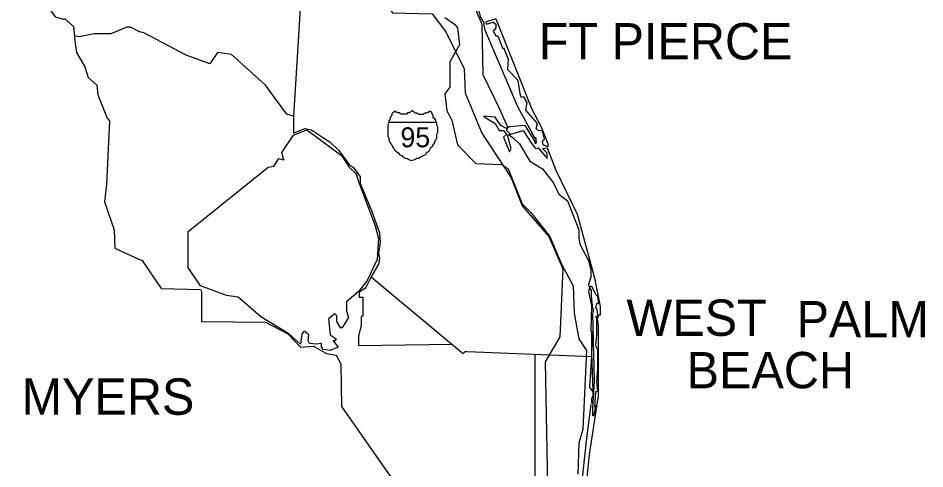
# Model space of a CAD drawing. Extents: x -820.2 to -798.1, y -2199.1 to -2182.2.
# Drawn here: x -805.79 to -804.667, y -2185.475 to -2184.917 of the extents above; entities that cross this region are included whole.
import ezdxf

# ---------------------------------------------------------------- set-up
doc = ezdxf.new("R2010")
doc.units = 0
for name, color, linetype in [('FLMap1', 7, 'Continuous'), ('FLMap2', 7, 'Continuous'), ('FLMap3', 7, 'Continuous'), ('TextMisc', 7, 'Continuous')]:
    doc.layers.add(name, color=color, linetype=linetype)

msp = doc.modelspace()

# ---------------------------------------------------------------- linework, layer by layer
at = {"layer": 'FLMap1'}
msp.add_line((-805.3303, -2185.0458), (-805.2728, -2185.0458), dxfattribs=at)
for points in [[(-805.3016, -2185.0319), (-805.3025, -2185.0319), (-805.304, -2185.0334), (-805.305, -2185.0344), (-805.3065, -2185.0344), (-805.3075, -2185.0344), (-805.3085, -2185.0358), (-805.31, -2185.0358), (-805.312, -2185.0358), (-805.3135, -2185.0358), (-805.3145, -2185.0358), (-805.3159, -2185.0358), (-805.3169, -2185.0344), (-805.3194, -2185.0344), (-805.3204, -2185.0334), (-805.3219, -2185.0334), (-805.3234, -2185.0319), (-805.3244, -2185.0334), (-805.3259, -2185.0344), (-805.3269, -2185.0358), (-805.3269, -2185.0368), (-805.3279, -2185.0398), (-805.3293, -2185.0408), (-805.3293, -2185.0433), (-805.3303, -2185.0443), (-805.3303, -2185.0468), (-805.3318, -2185.0492), (-805.3318, -2185.0517), (-805.3318, -2185.0537), (-805.3318, -2185.0562), (-805.3318, -2185.0587), (-805.3318, -2185.0611), (-805.3318, -2185.0631), (-805.3303, -2185.0656), (-805.3303, -2185.0681), (-805.3293, -2185.0706), (-805.3279, -2185.0726), (-805.3269, -2185.074), (-805.3259, -2185.0765), (-805.3244, -2185.0785), (-805.3234, -2185.08), (-805.3204, -2185.0825), (-805.3194, -2185.0835), (-805.3169, -2185.0864), (-805.3145, -2185.0874), (-805.3135, -2185.0884), (-805.311, -2185.0899), (-805.3085, -2185.0909), (-805.3075, -2185.0909), (-805.305, -2185.0924), (-805.3016, -2185.0934)], [(-805.3016, -2185.0319), (-805.3006, -2185.0319), (-805.2991, -2185.0334), (-805.2981, -2185.0344), (-805.2966, -2185.0344), (-805.2956, -2185.0344), (-805.2931, -2185.0358), (-805.2921, -2185.0358), (-805.2911, -2185.0358), (-805.2897, -2185.0358), (-805.2887, -2185.0358), (-805.2872, -2185.0358), (-805.2862, -2185.0344), (-805.2837, -2185.0344), (-805.2827, -2185.0334), (-805.2812, -2185.0334), (-805.2792, -2185.0319), (-805.2777, -2185.0334), (-805.2777, -2185.0344), (-805.2768, -2185.0358), (-805.2758, -2185.0368), (-805.2758, -2185.0398), (-805.2743, -2185.0408), (-805.2728, -2185.0433), (-805.2728, -2185.0443), (-805.2713, -2185.0468), (-805.2713, -2185.0492), (-805.2703, -2185.0517), (-805.2703, -2185.0537), (-805.2703, -2185.0562), (-805.2703, -2185.0587), (-805.2713, -2185.0611), (-805.2713, -2185.0631), (-805.2713, -2185.0656), (-805.2728, -2185.0681), (-805.2743, -2185.0706), (-805.2743, -2185.0726), (-805.2758, -2185.074), (-805.2768, -2185.0765), (-805.2792, -2185.0785), (-805.2802, -2185.08), (-805.2812, -2185.0825), (-805.2837, -2185.0835), (-805.2852, -2185.0864), (-805.2872, -2185.0874), (-805.2897, -2185.0884), (-805.2921, -2185.0899), (-805.2931, -2185.0909), (-805.2956, -2185.0909), (-805.2981, -2185.0924), (-805.3016, -2185.0934)], [(-805.4891, -2185.2869), (-805.5169, -2185.2626), (-805.5313, -2185.2606), (-805.5635, -2185.2487), (-805.5789, -2185.2259), (-805.5789, -2185.1812), (-805.4797, -2185.1018), (-805.4727, -2185.1003), (-805.4668, -2185.0909), (-805.4603, -2185.0924), (-805.4628, -2185.0835), (-805.4484, -2185.0621), (-805.432, -2185.0552), (-805.3889, -2185.0874), (-805.3794, -2185.1018), (-805.371, -2185.1098), (-805.368, -2185.1192), (-805.3472, -2185.1743), (-805.3432, -2185.1901), (-805.3447, -2185.2159), (-805.3576, -2185.2427), (-805.368, -2185.2556), (-805.3829, -2185.2685), (-805.3829, -2185.2799), (-805.3804, -2185.2879), (-805.3879, -2185.2998), (-805.3899, -2185.3013), (-805.3948, -2185.2928), (-805.3948, -2185.2859), (-805.3973, -2185.2834), (-805.4033, -2185.2879), (-805.4052, -2185.2894), (-805.4033, -2185.3092), (-805.3958, -2185.3142), (-805.3973, -2185.3166), (-805.3993, -2185.3166), (-805.3933, -2185.3246), (-805.4033, -2185.3286), (-805.4112, -2185.3276), (-805.4137, -2185.3246), (-805.4137, -2185.3201), (-805.4201, -2185.3211), (-805.4286, -2185.3201), (-805.4305, -2185.3166), (-805.4296, -2185.3092), (-805.4355, -2185.3047), (-805.438, -2185.3082), (-805.44, -2185.3211), (-805.4544, -2185.3082), (-805.4891, -2185.2869)]]:
    msp.add_lwpolyline(points, dxfattribs=at)
at = {"layer": 'FLMap2'}
for points in [[(-805.566, -2184.564), (-805.5625, -2184.6007), (-805.5452, -2184.631), (-805.5273, -2184.6702), (-805.5253, -2184.701), (-805.4975, -2184.7491), (-805.4891, -2184.7635), (-805.4821, -2184.7709), (-805.4881, -2184.7873), (-805.4509, -2184.8652), (-805.439, -2184.885), (-805.4484, -2185.0383), (-805.4484, -2185.0597), (-805.4345, -2185.0537), (-805.4261, -2185.0552), (-805.4127, -2185.0646)], [(-805.2911, -2184.7218), (-805.2812, -2184.7372), (-805.2634, -2184.7754), (-805.2574, -2184.7908), (-805.2465, -2184.828), (-805.2445, -2184.828), (-805.2371, -2184.8592), (-805.2336, -2184.8686), (-805.2361, -2184.8731), (-805.2202, -2184.9128), (-805.2152, -2184.9247), (-805.2142, -2184.9867), (-805.1939, -2185.0284), (-805.1835, -2185.0517)], [(-805.7902, -2184.7823), (-805.7868, -2184.7883), (-805.7868, -2184.7932), (-805.7878, -2184.7997), (-805.7714, -2184.827), (-805.7639, -2184.8384), (-805.7639, -2184.8677), (-805.7515, -2184.9044), (-805.7436, -2184.9153), (-805.7352, -2184.9178), (-805.7317, -2184.9178), (-805.7208, -2184.9272), (-805.7188, -2184.949), (-805.7173, -2184.9594), (-805.7069, -2184.9773), (-805.7029, -2184.9907), (-805.692, -2185.0001), (-805.691, -2185.012), (-805.6791, -2185.0408)], [(-805.2371, -2184.8245), (-805.2351, -2184.8424), (-805.2276, -2184.8731), (-805.2167, -2184.9163), (-805.2132, -2184.9222), (-805.2118, -2184.9307), (-805.1711, -2185.0264), (-805.1497, -2185.0656)], [(-805.4484, -2185.0358), (-805.4484, -2185.0383), (-805.4568, -2185.0358), (-805.4831, -2185.0001), (-805.5253, -2184.9619), (-805.5427, -2184.9594), (-805.5521, -2184.9738), (-805.5814, -2184.9629), (-805.634, -2184.9351), (-805.6394, -2184.9341), (-805.6503, -2184.9282), (-805.6548, -2184.9282), (-805.6746, -2184.9366), (-805.6955, -2184.9366), (-805.7138, -2184.9401), (-805.7198, -2184.9391)], [(-805.1979, -2184.9178), (-805.2108, -2184.9222), (-805.2093, -2184.9247), (-805.2013, -2184.9222), (-805.1979, -2184.9247), (-805.1979, -2184.9292), (-805.2013, -2184.9331), (-805.1979, -2184.9391), (-805.1954, -2184.9391), (-805.1894, -2184.955), (-805.1884, -2184.9535), (-805.1825, -2184.9679), (-805.1835, -2184.9808)], [(-805.1979, -2184.9178), (-805.1532, -2185.0299), (-805.1418, -2185.0517), (-805.1334, -2185.0726)], [(-805.1334, -2185.0726), (-805.1334, -2185.075), (-805.1334, -2185.0765), (-805.1393, -2185.074), (-805.1403, -2185.0691), (-805.1378, -2185.0671), (-805.1403, -2185.0572), (-805.1453, -2185.0562), (-805.1478, -2185.0537), (-805.1463, -2185.0477), (-805.1607, -2185.0309), (-805.1592, -2185.0215), (-805.1631, -2185.0145), (-805.1666, -2185.0155), (-805.1676, -2185.011), (-805.1701, -2184.9942), (-805.1835, -2184.9808)], [(-805.6791, -2185.0408), (-805.6766, -2185.0443), (-805.6801, -2185.1232), (-805.6826, -2185.1445), (-805.6707, -2185.1792), (-805.6697, -2185.202), (-805.6394, -2185.2159), (-805.6359, -2185.2174), (-805.6126, -2185.2521)], [(-805.1497, -2185.0656), (-805.1488, -2185.0646), (-805.1478, -2185.0706), (-805.1488, -2185.0726), (-805.1497, -2185.0691), (-805.1617, -2185.0502), (-805.181, -2185.0517), (-805.1845, -2185.0537), (-805.1919, -2185.0502), (-805.1989, -2185.0398), (-805.2132, -2185.0383), (-805.2073, -2185.0423), (-805.1989, -2185.0477), (-805.1939, -2185.0562), (-805.1884, -2185.0562), (-805.1845, -2185.0611), (-805.1884, -2185.0646), (-805.181, -2185.0825), (-805.179, -2185.0785), (-805.1835, -2185.0621), (-805.1641, -2185.0562), (-805.1532, -2185.0726), (-805.1488, -2185.0785), (-805.1453, -2185.0775), (-805.1344, -2185.0909), (-805.1344, -2185.0845), (-805.1403, -2185.0785), (-805.1344, -2185.0775)], [(-805.1835, -2185.0517), (-805.1845, -2185.0562), (-805.181, -2185.0597), (-805.181, -2185.0621), (-805.176, -2185.0656), (-805.1686, -2185.0726), (-805.1557, -2185.0944), (-805.1403, -2185.1038), (-805.1269, -2185.1207), (-805.12, -2185.1351), (-805.1091, -2185.1435), (-805.0952, -2185.1792), (-805.0952, -2185.1891), (-805.0937, -2185.1971), (-805.0833, -2185.2174), (-805.0803, -2185.2293), (-805.0803, -2185.2378), (-805.0833, -2185.2472), (-805.0818, -2185.2521), (-805.0833, -2185.2556), (-805.0793, -2185.2735), (-805.0803, -2185.3047), (-805.0793, -2185.3047), (-805.0793, -2185.336)], [(-805.4127, -2185.0646), (-805.4033, -2185.0706), (-805.3923, -2185.081), (-805.3794, -2185.0984), (-805.3745, -2185.1018), (-805.37, -2185.1078), (-805.3661, -2185.1137), (-805.3661, -2185.1217), (-805.3517, -2185.1554), (-805.3422, -2185.1832), (-805.3412, -2185.1951), (-805.3432, -2185.208), (-805.3422, -2185.2149), (-805.3432, -2185.2219), (-805.3517, -2185.2368), (-805.3586, -2185.2497), (-805.3601, -2185.2521), (-805.367, -2185.2566), (-805.367, -2185.2626), (-805.3626, -2185.2626), (-805.3626, -2185.2859), (-805.3646, -2185.2869), (-805.3646, -2185.2978), (-805.368, -2185.3107), (-805.368, -2185.3226), (-805.2514, -2185.3211)], [(-805.1344, -2185.0775), (-805.1234, -2185.1053), (-805.0972, -2185.1599), (-805.0818, -2185.2159), (-805.0743, -2185.2437)], [(-805.3517, -2185.2378), (-805.2405, -2185.331), (-805.2385, -2185.3325), (-805.2361, -2185.33), (-805.2336, -2185.33), (-805.0793, -2185.336)], [(-805.6126, -2185.2521), (-805.5635, -2185.2531), (-805.5625, -2185.2556), (-805.5625, -2185.2928), (-805.4831, -2185.2938), (-805.4554, -2185.3082), (-805.44, -2185.3246), (-805.4236, -2185.3236), (-805.4077, -2185.3325), (-805.3958, -2185.3345), (-805.3899, -2185.3454), (-805.3889, -2185.398), (-805.2713, -2185.5667), (-805.2599, -2185.6322), (-805.2584, -2185.7255)], [(-805.0709, -2185.2978), (-805.0719, -2185.2894), (-805.0709, -2185.2859), (-805.0719, -2185.2859), (-805.0743, -2185.2869), (-805.0733, -2185.2879), (-805.0733, -2185.3092), (-805.0743, -2185.3226), (-805.0719, -2185.3276), (-805.0719, -2185.331), (-805.0719, -2185.3514), (-805.0733, -2185.3677), (-805.0719, -2185.3792), (-805.0743, -2185.3801), (-805.0758, -2185.399), (-805.0743, -2185.3965), (-805.0758, -2185.405), (-805.0768, -2185.4099), (-805.0778, -2185.4099), (-805.0778, -2185.4), (-805.0758, -2185.3668), (-805.0778, -2185.2824), (-805.0768, -2185.2809), (-805.0768, -2185.277), (-805.0778, -2185.277), (-805.0793, -2185.2606), (-805.0793, -2185.2546), (-805.0818, -2185.2497), (-805.0793, -2185.2487), (-805.0743, -2185.2591), (-805.0719, -2185.2616), (-805.0709, -2185.271), (-805.0733, -2185.271), (-805.0743, -2185.276), (-805.0733, -2185.276), (-805.0719, -2185.2844), (-805.0684, -2185.2844), (-805.0684, -2185.2745), (-805.0709, -2185.2616), (-805.0743, -2185.2437)], [(-805.0917, -2185.5553), (-805.0818, -2185.4575), (-805.0709, -2185.3851), (-805.0709, -2185.2978)], [(-805.0793, -2185.3092), (-805.0778, -2185.3092), (-805.0793, -2185.3325), (-805.0778, -2185.3792)], [(-805.1497, -2185.3335), (-805.1497, -2185.5201), (-805.1488, -2185.6441), (-805.1522, -2185.6555), (-805.1512, -2185.7289)], [(-805.0793, -2185.336), (-805.0818, -2185.3742), (-805.0778, -2185.3801), (-805.0778, -2185.3851), (-805.0793, -2185.3886), (-805.0793, -2185.3945)], [(-805.0803, -2185.3955), (-805.0857, -2185.4372), (-805.0927, -2185.5017), (-805.1021, -2185.5677), (-805.1021, -2185.5726), (-805.1105, -2185.596), (-805.1081, -2185.6044), (-805.1105, -2185.6178), (-805.1185, -2185.6203), (-805.1185, -2185.6486), (-805.121, -2185.6595), (-805.121, -2185.7046), (-805.1234, -2185.7111), (-805.1334, -2185.7547), (-805.1403, -2185.7646), (-805.1438, -2185.8038), (-805.1428, -2185.8093), (-805.1453, -2185.8187), (-805.1726, -2185.8301), (-805.2023, -2185.8579), (-805.2227, -2185.906)]]:
    msp.add_lwpolyline(points, dxfattribs=at)
at = {"layer": 'FLMap3'}
for points in [[(-805.4692, -2184.817), (-805.4355, -2184.8662), (-805.4236, -2184.8696), (-805.3646, -2184.8711), (-805.3412, -2184.891), (-805.3259, -2184.9103), (-805.2768, -2184.9118), (-805.2599, -2184.9341), (-805.2371, -2184.9798), (-805.2361, -2185.0095), (-805.2152, -2185.0597), (-805.179, -2185.1147), (-805.1651, -2185.1495), (-805.1324, -2185.1877), (-805.115, -2185.2278), (-805.1185, -2185.3117), (-805.1368, -2185.3429), (-805.1334, -2185.5186)], [(-805.2609, -2184.9163), (-805.249, -2184.9247), (-805.2455, -2184.9292), (-805.243, -2184.95), (-805.2549, -2184.9713), (-805.2549, -2185.0026), (-805.2609, -2185.011), (-805.2584, -2185.0319), (-805.2524, -2185.0433), (-805.2455, -2185.074), (-805.2227, -2185.0969), (-805.1904, -2185.0984), (-805.1825, -2185.1038), (-805.1651, -2185.147), (-805.1547, -2185.1579), (-805.1309, -2185.1877), (-805.1165, -2185.2219), (-805.1021, -2185.2487), (-805.1011, -2185.2824), (-805.0952, -2185.3142), (-805.0857, -2185.3286), (-805.0902, -2185.4268), (-805.0952, -2185.4432), (-805.0962, -2185.4819)]]:
    msp.add_lwpolyline(points, dxfattribs=at)

# ---------------------------------------------------------------- texts
at = {"layer": 'TextMisc'}
for s, height, p in [('FT PIERCE', 0.045, (-805.1448, -2184.9682)), ('95', 0.0247, (-805.316, -2185.077)), ('WEST', 0.045, (-805.0362, -2185.3106)), ('PALM', 0.045, (-804.8255, -2185.3124)), ('BEACH', 0.045, (-804.9616, -2185.3756)), ('FT MYERS', 0.045, (-805.8755, -2185.4084))]:
    msp.add_text(s, height=height, dxfattribs=at).set_placement(p)

doc.saveas('drawing.dxf')
